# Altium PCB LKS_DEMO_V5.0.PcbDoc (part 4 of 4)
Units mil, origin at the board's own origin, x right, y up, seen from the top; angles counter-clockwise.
Board outline 5414.8 x 3354.56 mil, 2 copper layers (Top Layer, Bottom Layer); 131 components, 85 nets, 355 pads, 272 vias.
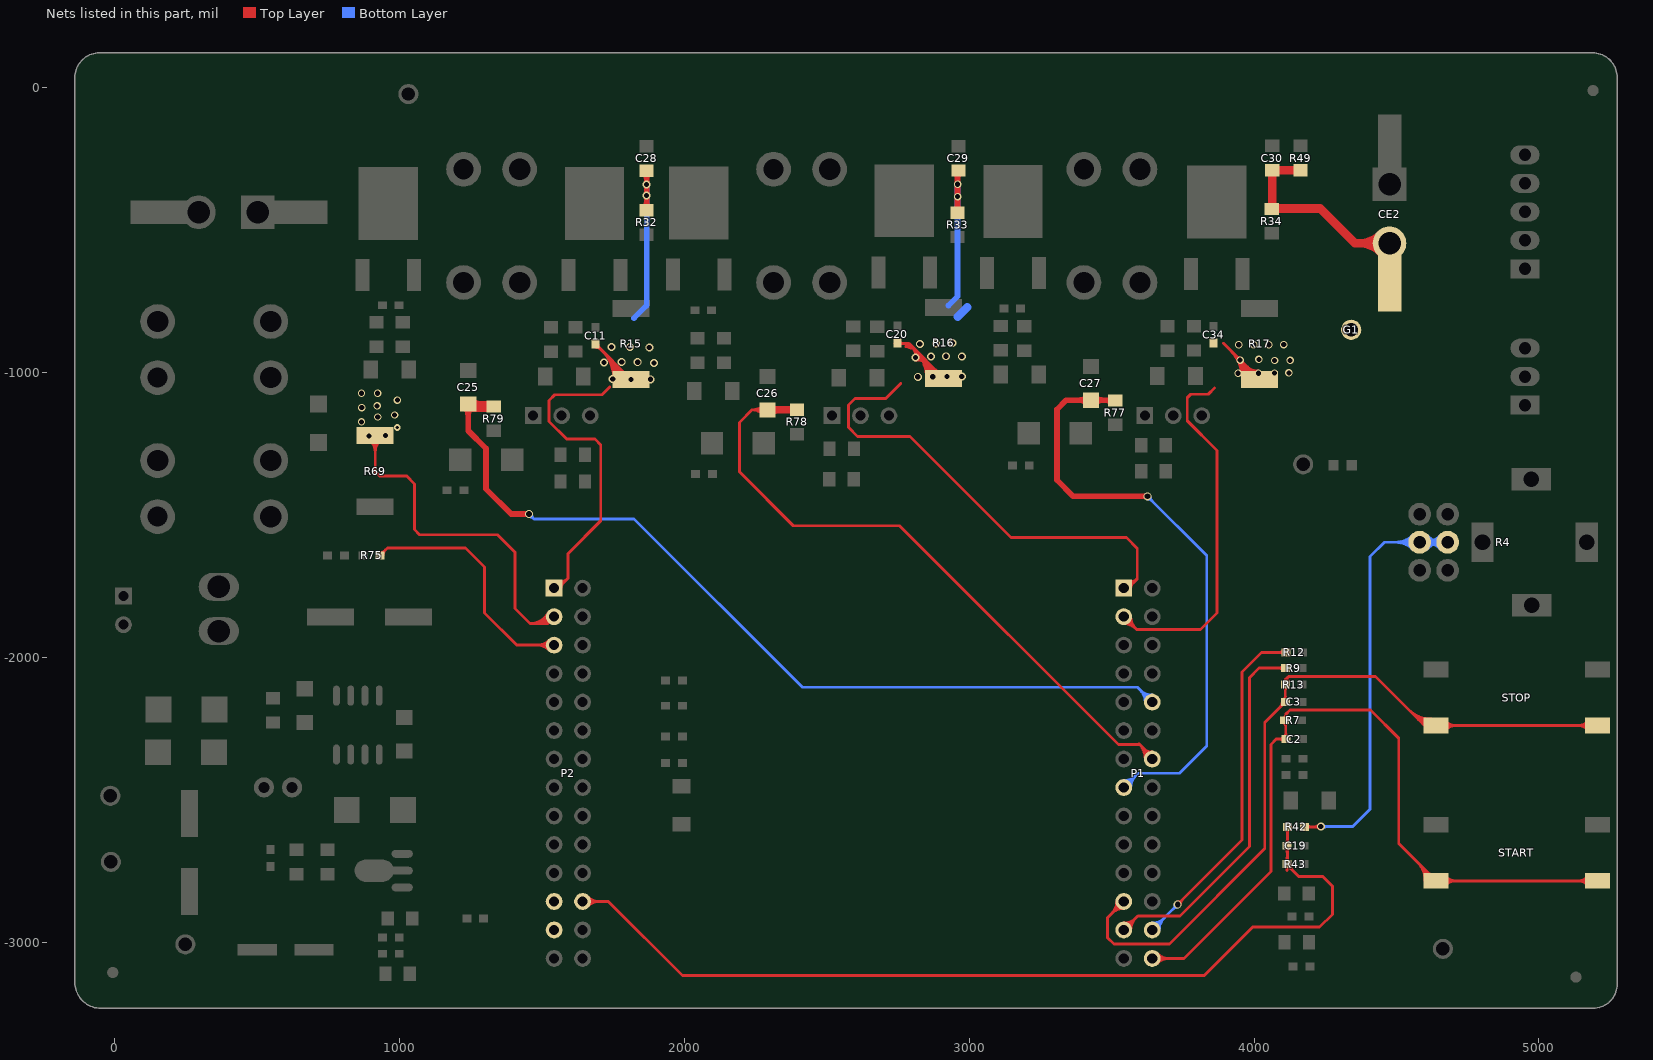
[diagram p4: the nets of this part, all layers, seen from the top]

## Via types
v1: diameter 26, hole 18, Top Layer to Bottom Layer, 117 vias
v2: diameter 28, hole 20, Top Layer to Bottom Layer, 77 vias
v3: diameter 28, hole 18, Top Layer to Bottom Layer, 73 vias
v4: diameter 23.62, hole 11.81, Top Layer to Bottom Layer, 5 vias

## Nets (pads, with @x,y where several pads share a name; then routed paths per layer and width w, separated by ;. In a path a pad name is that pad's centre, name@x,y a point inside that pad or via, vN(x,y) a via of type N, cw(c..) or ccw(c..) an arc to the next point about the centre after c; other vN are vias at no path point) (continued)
PGND: C11.2 C20.2 C28.1 C29.1 C30.1 C34.2 CE2.2 G1.1 P1.1 P1.2 P2.1 P2.2 R15.2 R16.1 R17.2 R32.1 R33.1 R34.1 R49.2 R69.1 | length 13563.9
  Top Layer w10: R69.1@914.27,-1220.9 914.27,-1347.89 930,-1363.63 1025.03,-1363.63 1052.09,-1390.69 1052.09,-1551.41 1070.11,-1569.43 1343.41,-1569.43 1404.57,-1630.58 1404.57,-1827.8 1457.84,-1881.07 1521.32,-1881.07 ; P2.1@1552.3,-1760.99 1590.81,-1722.48 ; C11.2@1686.48,-898.64 v3(1812.36,-1024.52) ; 1737.64,-1050.46 1710.19,-1077.91 1544.55,-1077.91 1524.89,-1097.56 1524.89,-1171.55 1586.49,-1233.15 1685.56,-1233.15 1706.23,-1253.82 1706.23,-1520.42 1590.81,-1635.84 1590.81,-1722.48 ; C20.2@2739.08,-898.48 2788.81,-898.48 R16.1@2909.76,-1019.43 ; 2759.24,-1038.12 2706.6,-1090.75 2598.05,-1090.75 2575.35,-1113.45 2575.35,-1191.92 2607.79,-1224.36 2791.94,-1224.36 3146.77,-1579.2 3551.29,-1579.2 3589.68,-1617.58 3589.68,-1723.64 ; P1.2@3542.25,-1856.82 3587.36,-1901.93 3812,-1901.93 3869.76,-1844.18 3869.76,-1273.79 3765.24,-1169.27 3765.24,-1088.38 3777.42,-1076.19 3838.74,-1076.19 3860.58,-1054.36 ; P1.1@3542.25,-1756.82 3556.5,-1756.82 3589.68,-1723.64 ; 3891.88,-896.92 R17.2@4018.89,-1023.93 ; 914.27,-1280.11 ccw(c855.06,-1280.11) 896.93,-1238.24 cw(c855.06,-1280.11) 914.27,-1280.11 ; 914.27,-1280.11 cw(c973.49,-1280.11) 931.61,-1238.24 ccw(c973.49,-1280.11) 914.27,-1280.11 ; 914.27,-1255.97 ccw(c879.2,-1255.97) 904,-1231.17 cw(c879.2,-1255.97) 914.27,-1255.97 ; 914.27,-1255.97 cw(c949.34,-1255.97) 924.54,-1231.17 ccw(c949.34,-1255.97) 914.27,-1255.97 ; 1590.81,-1722.49 cw(c1560.81,-1692.49) 1549.05,-1733.25 ccw(c1560.81,-1692.49) 1590.81,-1722.49 ; R15.2@1796.99,-1009.15 ccw(c1812.36,-993.79) 1812.36,-1015.52 cw(c1812.36,-993.79) R15.2@1796.99,-1009.15 ; R15.2@1796.99,-1009.15 cw(c1781.63,-1024.52) 1803.36,-1024.52 ccw(c1781.63,-1024.52) R15.2@1796.99,-1009.15 ; 2777.12,-901.14 ccw(c2799.64,-888.13) 2792.91,-913.25 ; 2777.12,-901.14 ccw(c2799.64,-888.13) 2792.91,-913.25 ; 2777.12,-901.14 ccw(c2799.64,-888.13) 2792.91,-913.25 ; 2778.18,-909.31 cw(c2778.18,-961.11) 2814.81,-924.48 ; 2778.18,-909.31 cw(c2778.18,-961.11) 2814.81,-924.48 ; 2778.18,-909.31 cw(c2778.18,-961.11) 2814.81,-924.48 ; 2778.18,-899.31 cw(c2778.18,-926.97) 2797.74,-907.41 ; 2778.18,-899.31 cw(c2778.18,-926.97) 2797.74,-907.41 ; 2778.18,-899.31 cw(c2778.18,-926.97) 2797.74,-907.41 ; 2778.25,-899.31 cw(c2776.95,-920.6) 2795.43,-909.93 ; 2778.25,-899.31 cw(c2776.95,-920.6) 2795.43,-909.93 ; 2778.25,-899.31 cw(c2776.95,-920.6) 2795.43,-909.93 ; 3567.05,-1881.62 ccw(c3542.25,-1906.42) 3542.25,-1871.34 cw(c3542.25,-1906.42) 3567.05,-1881.62 ; 3567.05,-1881.62 cw(c3591.85,-1856.82) 3556.78,-1856.82 ccw(c3591.85,-1856.82) 3567.05,-1881.62 ; 3584.12,-1898.69 ccw(c3542.25,-1940.56) 3542.25,-1881.34 cw(c3542.25,-1940.56) 3584.12,-1898.69 ; 3584.12,-1898.69 cw(c3625.99,-1856.82) 3566.78,-1856.82 ccw(c3625.99,-1856.82) 3584.12,-1898.69 ; 3589.67,-1723.64 cw(c3561.6,-1695.57) 3549.64,-1733.43 ccw(c3561.6,-1695.57) 3589.67,-1723.64 ; 1457.84,-1881.07 ccw(c1457.84,-1808.19) 1521,-1844.57 cw(c1457.84,-1808.19) 1457.84,-1881.07 ; 1475.14,-1881.07 ccw(c1475.14,-1818.16) 1529.66,-1849.56 cw(c1475.14,-1818.16) 1475.14,-1881.07 ; 1492.45,-1881.07 ccw(c1492.45,-1828.13) 1538.33,-1854.56 cw(c1492.45,-1828.13) 1492.45,-1881.07 ; 1509.75,-1881.07 ccw(c1509.75,-1838.09) 1546.99,-1859.55 cw(c1509.75,-1838.09) 1509.75,-1881.07 ; P2.1@1546.28,-1742.86 ccw(c1555.45,-1711.08) 1578.83,-1734.47 cw(c1555.45,-1711.08) P2.1@1546.28,-1742.86 ; P2.1@1566.78,-1756.82 cw(c1591.63,-1756.82) 1574.06,-1739.24 ccw(c1591.63,-1756.82) P2.1@1566.78,-1756.82 ; C11.2@1687.64,-911.18 cw(c1687.64,-938.66) 1707.07,-919.23 ccw(c1687.64,-938.66) C11.2@1687.64,-911.18 ; C11.2@1696.42,-902.4 ccw(c1711.33,-902.4) 1700.78,-912.94 cw(c1711.33,-902.4) C11.2@1696.42,-902.4 ; 1710,-922.16 cw(c1607.64,-1024.52) 1752.4,-1024.52 ccw(c1607.64,-1024.52) 1710,-922.16 ; 1727.07,-939.23 cw(c1641.78,-1024.52) 1762.4,-1024.52 ccw(c1641.78,-1024.52) 1727.07,-939.23 ; 1744.14,-956.3 cw(c1675.92,-1024.52) 1772.4,-1024.52 ccw(c1675.92,-1024.52) 1744.14,-956.3 ; 1761.21,-973.37 cw(c1710.07,-1024.52) 1782.4,-1024.52 ccw(c1710.07,-1024.52) 1761.21,-973.37 ; 1778.28,-990.44 cw(c1744.21,-1024.52) 1792.4,-1024.52 ccw(c1744.21,-1024.52) 1778.28,-990.44 ; C20.2@2753.73,-903.53 cw(c2765.92,-915.73) 2765.92,-898.48 ccw(c2765.92,-915.73) C20.2@2753.73,-903.53 ; C20.2@2753.73,-891.12 ccw(c2771.51,-873.34) 2771.51,-898.48 cw(c2771.51,-873.34) C20.2@2753.73,-891.12 ; 2794.48,-904.15 cw(c2751.96,-946.66) 2812.09,-946.66 ccw(c2751.96,-946.66) 2794.48,-904.15 ; 2806.96,-916.63 cw(c2702.58,-1021) 2850.19,-1021 ccw(c2702.58,-1021) 2806.96,-916.63 ; v3@2811.09,-955.66 cw(c2811.09,-1039.93) 2870.67,-980.34 ccw(c2811.09,-1039.93) v3@2811.09,-955.66 ; v3@2811.09,-945.66 cw(c2811.09,-1005.79) 2853.6,-963.27 ccw(c2811.09,-1005.79) v3@2811.09,-945.66 ; v3@2811.09,-935.66 cw(c2811.09,-971.65) 2836.53,-946.2 ccw(c2811.09,-971.65) v3@2811.09,-935.66 ; 2811.55,-921.22 cw(c2786.1,-946.66) 2822.09,-946.66 ccw(c2786.1,-946.66) 2811.55,-921.22 ; 2824.03,-933.7 cw(c2736.72,-1021) 2860.19,-1021 ccw(c2736.72,-1021) 2824.03,-933.7 ; 2841.1,-950.77 cw(c2770.87,-1021) 2870.19,-1021 ccw(c2770.87,-1021) 2841.1,-950.77 ; 2858.17,-967.84 cw(c2805.01,-1021) 2880.19,-1021 ccw(c2805.01,-1021) 2858.17,-967.84 ; 2875.24,-984.91 cw(c2839.15,-1021) 2890.19,-1021 ccw(c2839.15,-1021) 2875.24,-984.91 ; 2876.27,-985.94 ccw(c2921.84,-940.37) 2921.84,-1004.82 cw(c2921.84,-940.37) 2876.27,-985.94 ; R16.1@2893.34,-1003.01 ccw(c2921.84,-974.51) 2921.84,-1014.82 cw(c2921.84,-974.51) R16.1@2893.34,-1003.01 ; P1.1@3546.63,-1742.96 ccw(c3556.01,-1713.27) 3578.03,-1735.29 cw(c3556.01,-1713.27) P1.1@3546.63,-1742.96 ; P1.1@3566.78,-1756.82 cw(c3591.58,-1756.82) 3574.04,-1739.28 ccw(c3591.58,-1756.82) P1.1@3566.78,-1756.82 ; 3916.32,-921.36 cw(c3813.16,-1024.52) 3959.05,-1024.52 ccw(c3813.16,-1024.52) 3916.32,-921.36 ; 3933.39,-938.43 cw(c3847.31,-1024.52) 3969.05,-1024.52 ccw(c3847.31,-1024.52) 3933.39,-938.43 ; 3936.81,-941.84 cw(c3922.35,-956.3) 3942.8,-956.3 ccw(c3922.35,-956.3) 3936.81,-941.84 ; 3937.94,-942.97 ccw(c3950.8,-930.11) 3950.8,-948.3 cw(c3950.8,-930.11) 3937.94,-942.97 ; v1@3950.47,-955.5 cw(c3881.45,-1024.52) 3979.05,-1024.52 ccw(c3881.45,-1024.52) v1@3950.47,-955.5 ; v1@3950.8,-964.3 cw(c3950.8,-984.74) 3965.25,-970.29 ccw(c3950.8,-984.74) v1@3950.8,-964.3 ; v1@3958.8,-956.3 ccw(c3976.98,-956.3) 3964.12,-969.16 cw(c3976.98,-956.3) v1@3958.8,-956.3 ; 3967.54,-972.57 cw(c3915.59,-1024.52) 3989.05,-1024.52 ccw(c3915.59,-1024.52) 3967.54,-972.57 ; 3971.3,-976.34 ccw(c4015.34,-932.3) 4015.34,-994.58 cw(c4015.34,-932.3) 3971.3,-976.34 ; 3984.61,-989.64 cw(c3949.73,-1024.52) 3999.05,-1024.52 ccw(c3949.73,-1024.52) 3984.61,-989.64 ; 3988.37,-993.41 ccw(c4015.34,-966.44) 4015.34,-1004.58 cw(c4015.34,-966.44) 3988.37,-993.41
  Top Layer w20: R32.1@1866.99,-429.93 C28.1@1866.99,-290.99 ; R33.1@2958.76,-438.55 C29.1@2958.76,-300.89 ; 1866.99,-401.8 ccw(c1895.13,-401.8) 1875.23,-421.69 cw(c1895.13,-401.8) 1866.99,-401.8 ; 1866.99,-401.8 cw(c1838.86,-401.8) 1858.75,-421.69 ccw(c1838.86,-401.8) 1866.99,-401.8 ; 1866.99,-319.13 ccw(c1838.86,-319.13) 1858.75,-299.24 cw(c1838.86,-319.13) 1866.99,-319.13 ; 1866.99,-319.13 cw(c1895.13,-319.13) 1875.23,-299.24 ccw(c1895.13,-319.13) 1866.99,-319.13 ; C29.1@2950.41,-298.91 cw(c2930.24,-319.08) 2958.76,-319.08 ccw(c2930.24,-319.08) C29.1@2950.41,-298.91 ; R33.1@2950.54,-430.33 ccw(c2930.7,-410.49) 2958.76,-410.49 cw(c2930.7,-410.49) R33.1@2950.54,-430.33 ; 2958.76,-410.39 ccw(c2986.97,-410.39) 2967.02,-430.33 cw(c2986.97,-410.39) 2958.76,-410.39 ; 2958.76,-318.53 cw(c2986.5,-318.53) 2966.89,-298.91 ccw(c2986.5,-318.53) 2958.76,-318.53
  Top Layer w30: C30.1@4063.55,-289.6 4063.55,-423.88 4232.02,-423.88 4354.04,-545.9 CE2.2@4475.37,-545.9 ; C30.1@4063.76,-289.81 R49.2@4162.89,-289.81 ; 4369.02,-545.9 ccw(c4369.02,-439.54) 4444.22,-514.74 cw(c4369.02,-439.54) 4369.02,-545.9 ; 4369.02,-545.9 cw(c4369.02,-652.25) 4444.22,-577.05 ccw(c4369.02,-652.25) 4369.02,-545.9
  Bottom Layer w20: 1822.76,-808.82 1866.99,-764.58 v3@1866.99,-342.17 ; 2927,-764.3 2958.81,-732.5 v1(2958.81,-339)
  Bottom Layer w30: 2959.7,-803.54 2993.28,-769.96
  other v1: 892.64,-1222.76 949.94,-1220.9 866.13,-1173.28 922.99,-1156.02 982.37,-1149.02 866.77,-1122.82 921.06,-1117.07 991.96,-1096.63 866.12,-1072.37 922.84,-1072.41 3943.71,-1002.58 4015.34,-1002.58 4071.43,-1001.56 4121.77,-1001.22 4071.77,-957.63 4126.16,-956.96 3950.8,-956.3 4016.35,-953.59 3945.75,-902.24 3998.44,-901.89 4051.83,-902.23 4103.86,-901.89 2958.82,-382.12
  other v3: 1881.29,-1023.49 1747.93,-1022.53 2819.11,-1014.82 2871.72,-1014.82 2921.84,-1013.81 2973.45,-1013.31 1892.32,-966.4 1717.71,-964 1835.72,-963.53 1779.59,-962.57 2811.09,-946.66 2865.21,-943.66 2973.45,-943.15 2918.33,-942.65 1876.49,-912.2 1744.1,-910.76 1807.89,-910.28 2826.12,-899.06 2882.75,-898.05 2940.38,-896.55 1866.99,-378.39 1866.99,-339.36
  other v4: 991.83,-1192.69
RXD0: P1.13 R9.1 | length 1658
  Top Layer w10: P1.13@3542.25,-2956.82 3591.58,-2907.48 3739.73,-2907.48 3983.31,-2663.9 3983.31,-2071.55 4017.54,-2037.33 R9.1@4109.61,-2037.33 ; 3567.05,-2932.02 ccw(c3591.85,-2956.82) 3556.78,-2956.82 cw(c3591.85,-2956.82) 3567.05,-2932.02 ; 3567.05,-2932.02 cw(c3542.25,-2907.22) 3542.25,-2942.29 ccw(c3542.25,-2907.22) 3567.05,-2932.02 ; 3584.12,-2914.94 ccw(c3625.99,-2956.82) 3566.78,-2956.82 cw(c3625.99,-2956.82) 3584.12,-2914.94 ; 3584.12,-2914.94 cw(c3542.25,-2873.07) 3542.25,-2932.29 ccw(c3542.25,-2873.07) 3584.12,-2914.94 ; 4086.45,-2037.33 ccw(c4086.45,-2016.13) 4101.44,-2031.12 cw(c4086.45,-2016.13) 4086.45,-2037.33 ; 4086.45,-2037.33 cw(c4086.45,-2058.52) 4101.44,-2043.54 ccw(c4086.45,-2058.52) 4086.45,-2037.33
RXD1: P2.12
SPIN: C19.2 P2.26 R42.2 R43.2 | length 3870.8
  Top Layer w10: P2.26@1642.25,-2856.82 1732.3,-2856.82 1992.58,-3117.09 3825.04,-3117.09 3995.12,-2947.01 4229.81,-2947.01 4274.61,-2902.21 4274.61,-2803.4 4240.64,-2769.43 4156.27,-2769.43 R43.2@4115.46,-2728.62 ; R43.2@4109.02,-2731.94 cw(c4092.77,-2748.18) 4115.74,-2748.18 ; R43.2@4109.02,-2719.52 ccw(c4092.77,-2703.28) 4115.74,-2703.28 ; R42.2@4109.34,-2600.99 cw(c4092.05,-2618.27) 4116.49,-2618.27 ; C19.2@4109.54,-2655.11 ccw(c4092.74,-2638.32) 4116.49,-2638.32 ; R43.2@4110.98,-2719.52 ccw(c4097.68,-2706.22) 4116.49,-2706.22 ; R43.2@4111.22,-2722.41 ccw(c4098.48,-2709.68) 4116.49,-2709.68 ; 4115.74,-2745.67 cw(c4135.16,-2745.67) R43.2@4121.43,-2731.94 ; 4115.74,-2705.79 ccw(c4135.16,-2705.79) R43.2@4121.43,-2719.52 ; R43.2@4116.49,-2728.62 R42.2@4116.49,-2597.15 ; 4116.49,-2705.17 ccw(c4140.87,-2705.17) R43.2@4123.63,-2722.41 ; 4116.49,-2702.85 ccw(c4140.07,-2702.85) R43.2@4123.4,-2719.52 ; 4116.49,-2684.33 ccw(c4092.74,-2684.33) 4109.54,-2667.53 cw(c4094.55,-2682.52) 4115.74,-2682.52 cw(c4136.94,-2682.52) 4121.95,-2667.53 ccw(c4135.13,-2680.71) 4116.49,-2680.71 ; 4116.49,-2641.94 ccw(c4135.13,-2641.94) C19.2@4121.95,-2655.11 ; 4116.49,-2613.68 cw(c4134.44,-2613.68) R42.2@4121.75,-2600.99 ; R43.2@4117.43,-2737.4 cw(c4117.43,-2753.84) 4129.05,-2742.22 ; R43.2@4125.97,-2725.73 ccw(c4158.33,-2725.73) 4135.45,-2748.61 ; R43.2@4126.21,-2728.62 ccw(c4152.15,-2728.62) 4133.81,-2746.97 ; 1677.32,-2856.82 ccw(c1677.32,-2891.89) 1652.52,-2867.09 cw(c1677.32,-2891.89) 1677.32,-2856.82 ; 1677.32,-2856.82 cw(c1677.32,-2821.74) 1652.52,-2846.54 ccw(c1677.32,-2821.74) 1677.32,-2856.82 ; 1701.46,-2856.82 ccw(c1701.46,-2916.03) 1659.59,-2874.16 cw(c1701.46,-2916.03) 1701.46,-2856.82 ; 1701.46,-2856.82 cw(c1701.46,-2797.6) 1659.59,-2839.47 ccw(c1701.46,-2797.6) 1701.46,-2856.82
START1: C2.2 P1.28 R7.2 START.2 START.4 | length 4050.8
  Top Layer w10: P1.28@3642.25,-3056.82 3753.28,-3056.82 4058.77,-2751.32 4058.77,-2305.73 4077.8,-2286.71 C2.2@4110.99,-2286.71 4110.99,-2199.48 ; START.2@4619,-2785.42 START.4@5183.95,-2785.42 ; START.2@4638.66,-2784.03 4507.7,-2653.07 4507.7,-2283.96 4408.4,-2184.67 4125.8,-2184.67 4110.99,-2199.48 ; 3677.32,-3056.82 ccw(c3677.32,-3091.89) 3652.52,-3067.09 cw(c3677.32,-3091.89) 3677.32,-3056.82 ; 3677.32,-3056.82 cw(c3677.32,-3021.74) 3652.52,-3046.54 ccw(c3677.32,-3021.74) 3677.32,-3056.82 ; 3701.46,-3056.82 ccw(c3701.46,-3116.03) 3659.59,-3074.16 cw(c3701.46,-3116.03) 3701.46,-3056.82 ; 3701.46,-3056.82 cw(c3701.46,-2997.6) 3659.59,-3039.47 ccw(c3701.46,-2997.6) 3701.46,-3056.82 ; 4087.82,-2286.71 ccw(c4087.82,-2265.51) 4102.81,-2280.5 cw(c4087.82,-2265.51) 4087.82,-2286.71 ; 4087.82,-2286.71 cw(c4087.82,-2307.9) 4102.81,-2292.92 ccw(c4087.82,-2307.9) 4087.82,-2286.71 ; 4110.99,-2265.51 ccw(c4132.18,-2265.51) 4117.2,-2280.5 cw(c4132.18,-2265.51) 4110.99,-2265.51 ; 4110.99,-2265.51 cw(c4089.79,-2265.51) 4104.78,-2280.5 ccw(c4089.79,-2265.51) 4110.99,-2265.51 ; 4110.99,-2199.48 cw(c4092.87,-2199.48) 4103.89,-2213.86 ccw(c4092.87,-2199.48) 4110.99,-2199.48 ; R7.2@4103.02,-2227.04 cw(c4083.79,-2246.27) 4110.99,-2246.27 ccw(c4083.79,-2246.27) R7.2@4103.02,-2227.04 ; 4110.99,-2237.78 cw(c4126.18,-2237.78) 4115.44,-2227.04 ccw(c4126.18,-2237.78) 4110.99,-2237.78 ; 4110.99,-2203.88 ccw(c4126.18,-2203.88) 4115.44,-2214.62 cw(c4126.18,-2203.88) 4110.99,-2203.88 ; 4573.27,-2718.63 cw(c4507.87,-2784.03) 4600.35,-2784.03 ccw(c4507.87,-2784.03) 4573.27,-2718.63 ; 4590.34,-2735.7 cw(c4542.01,-2784.03) 4610.35,-2784.03 ccw(c4542.01,-2784.03) 4590.34,-2735.7 ; 4607.41,-2752.78 cw(c4576.16,-2784.03) 4620.35,-2784.03 ccw(c4576.16,-2784.03) 4607.41,-2752.78 ; START.2@4611.43,-2756.8 ccw(c4622.85,-2745.37) 4622.85,-2761.53 cw(c4622.85,-2745.37) START.2@4611.43,-2756.8 ; START.2@4663.31,-2775.19 ccw(c4688.01,-2750.48) 4688.01,-2785.42 cw(c4688.01,-2750.48) START.2@4663.31,-2775.19 ; START.2@4670.38,-2799.94 cw(c4705.42,-2834.98) 4705.42,-2785.42 ccw(c4705.42,-2834.98) START.2@4670.38,-2799.94 ; START.2@4670.38,-2768.12 ccw(c4712.16,-2726.34) 4712.16,-2785.42 cw(c4712.16,-2726.34) START.2@4670.38,-2768.12 ; 5132.09,-2785.42 ccw(c5132.09,-2726.34) 5173.87,-2768.12 cw(c5132.09,-2726.34) 5132.09,-2785.42 ; 5138.83,-2785.42 cw(c5138.83,-2834.98) 5173.87,-2799.94 ccw(c5138.83,-2834.98) 5138.83,-2785.42 ; 5156.23,-2785.42 ccw(c5156.23,-2750.48) 5180.94,-2775.19 cw(c5156.23,-2750.48) 5156.23,-2785.42
STOP1: C3.1 P1.12 R13.1 STOP.2 STOP.4 | length 4296.6
  Top Layer w10: P1.12@3542.25,-2856.82 3484.5,-2914.57 3484.5,-2983.05 3507.44,-3005.98 3702.22,-3005.98 4036.94,-2671.26 4036.94,-2228.44 C3.1@4109.35,-2156.04 R13.1@4109.35,-2095.34 4109.35,-2077.64 ; STOP.2@4617.02,-2258.15 4425.57,-2066.7 4120.28,-2066.7 ; STOP.2@4617.02,-2239 STOP.4@5183.95,-2239 ; 3500.38,-2898.69 ccw(c3458.51,-2856.82) 3517.72,-2856.82 cw(c3458.51,-2856.82) 3500.38,-2898.69 ; 3500.38,-2898.69 cw(c3542.25,-2940.56) 3542.25,-2881.34 ccw(c3542.25,-2940.56) 3500.38,-2898.69 ; 3517.45,-2881.62 ccw(c3492.65,-2856.82) 3527.72,-2856.82 cw(c3492.65,-2856.82) 3517.45,-2881.62 ; 3517.45,-2881.62 cw(c3542.25,-2906.42) 3542.25,-2871.34 ccw(c3542.25,-2906.42) 3517.45,-2881.62 ; 4109.35,-2134.85 ccw(c4130.54,-2134.85) 4115.55,-2149.83 cw(c4130.54,-2134.85) 4109.35,-2134.85 ; 4109.35,-2134.85 cw(c4088.15,-2134.85) 4103.14,-2149.83 ccw(c4088.15,-2134.85) 4109.35,-2134.85 ; 4109.35,-2116.54 ccw(c4088.15,-2116.54) 4103.14,-2101.55 cw(c4088.15,-2116.54) 4109.35,-2116.54 ; 4109.35,-2116.54 cw(c4130.54,-2116.54) 4115.55,-2101.55 ccw(c4130.54,-2116.54) 4109.35,-2116.54 ; 4109.35,-2077.64 ccw(c4122.81,-2077.64) 4114.66,-2088.35 cw(c4122.81,-2077.64) 4109.35,-2077.64 ; 4109.34,-2077.64 cw(c4095.88,-2077.64) 4104.03,-2088.35 ccw(c4095.88,-2077.64) 4109.34,-2077.64 ; 4109.35,-2077.64 4120.28,-2066.7 ; 4120.28,-2066.7 ccw(c4133.11,-2079.53) 4118.42,-2090.19 cw(c4133.11,-2079.53) 4120.28,-2066.7 ; 4091,-2174.39 ccw(c4072.65,-2156.04) 4098.6,-2156.04 cw(c4072.65,-2156.04) 4091,-2174.39 ; C3.1@4095.75,-2169.64 cw(c4107.38,-2181.27) 4107.38,-2164.82 ccw(c4107.38,-2181.27) C3.1@4095.75,-2169.64 ; R13.1@4110.33,-2096.06 cw(c4123.51,-2086.5) 4111.99,-2074.99 ccw(c4123.51,-2086.5) R13.1@4110.33,-2096.06 ; 4542.1,-2183.23 ccw(c4622.85,-2102.47) 4622.85,-2216.68 cw(c4622.85,-2102.47) 4542.1,-2183.23 ; 4559.17,-2200.3 ccw(c4622.85,-2136.61) 4622.85,-2226.68 cw(c4622.85,-2136.61) 4559.17,-2200.3 ; 4576.24,-2217.37 ccw(c4622.85,-2170.76) 4622.85,-2236.68 cw(c4622.85,-2170.76) 4576.24,-2217.37 ; 4593.31,-2234.44 ccw(c4622.85,-2204.9) 4622.85,-2246.68 cw(c4622.85,-2204.9) 4593.31,-2234.44 ; STOP.2@4663.31,-2248.02 cw(c4685.08,-2269.79) 4685.08,-2239 ccw(c4685.08,-2269.79) STOP.2@4663.31,-2248.02 ; STOP.2@4663.31,-2230.34 ccw(c4684.21,-2209.43) 4684.21,-2239 cw(c4684.21,-2209.43) STOP.2@4663.31,-2230.34 ; STOP.2@4670.38,-2255.09 cw(c4709.22,-2293.93) 4709.22,-2239 ccw(c4709.22,-2293.93) STOP.2@4670.38,-2255.09 ; STOP.2@4670.38,-2223.27 ccw(c4708.35,-2185.29) 4708.35,-2239 cw(c4708.35,-2185.29) STOP.2@4670.38,-2223.27 ; 5135.03,-2239 cw(c5135.03,-2293.93) 5173.87,-2255.09 ccw(c5135.03,-2293.93) 5135.03,-2239 ; 5135.89,-2239 ccw(c5135.89,-2185.29) 5173.87,-2223.27 cw(c5135.89,-2185.29) 5135.89,-2239 ; 5159.17,-2239 cw(c5159.17,-2269.79) 5180.94,-2248.02 ccw(c5159.17,-2269.79) 5159.17,-2239 ; 5160.04,-2239 ccw(c5160.04,-2209.43) 5180.94,-2230.34 cw(c5160.04,-2209.43) 5160.04,-2239
TXD0: P1.27 R12.2 | length 1717.5
  Top Layer w10: v2(3731.35,-2867.74) 3957.86,-2641.22 3957.86,-2050.75 4026.14,-1982.47 R12.2@4110.99,-1982.47 ; 3746.71,-2852.37 ccw(c3762.07,-2867.74) 3740.35,-2867.74 cw(c3762.07,-2867.74) 3746.71,-2852.37 ; 3746.71,-2852.37 cw(c3731.35,-2837.01) 3731.35,-2858.74 ccw(c3731.35,-2837.01) 3746.71,-2852.37 ; 4087.82,-1982.47 ccw(c4087.82,-1961.28) 4102.81,-1976.27 cw(c4087.82,-1961.28) 4087.82,-1982.47 ; 4087.82,-1982.47 cw(c4087.82,-2003.67) 4102.81,-1988.68 ccw(c4087.82,-2003.67) 4087.82,-1982.47
  Bottom Layer w10: P1.27@3642.25,-2956.82 v2(3731.35,-2867.74) ; 3667.05,-2932.02 ccw(c3691.85,-2956.82) 3656.78,-2956.82 cw(c3691.85,-2956.82) 3667.05,-2932.02 ; 3667.05,-2932.02 cw(c3642.25,-2907.22) 3642.25,-2942.29 ccw(c3642.25,-2907.22) 3667.05,-2932.02 ; 3684.12,-2914.94 ccw(c3725.99,-2956.82) 3666.78,-2956.82 cw(c3725.99,-2956.82) 3684.12,-2914.94 ; 3684.12,-2914.94 cw(c3642.25,-2873.07) 3642.25,-2932.29 ccw(c3642.25,-2873.07) 3684.12,-2914.94 ; 3715.95,-2883.11 cw(c3731.35,-2898.51) 3731.35,-2876.74 ccw(c3731.35,-2898.51) 3715.95,-2883.11 ; 3715.99,-2883.07 ccw(c3700.66,-2867.74) 3722.35,-2867.74 cw(c3700.66,-2867.74) 3715.99,-2883.07
TXD1: P2.13
VB1: C27.1 P1.8 R77.1 | length 2834.8
  Top Layer w20: R77.1@3511.39,-1097.1 C27.1@3427.06,-1097.1 3339.81,-1097.1 3307.7,-1129.21 3307.7,-1377.36 3364.86,-1434.52 v2(3625.43,-1434.52) ; 3385.07,-1097.1 ccw(c3385.07,-1057.08) 3413.37,-1085.38 cw(c3385.07,-1057.08) 3385.07,-1097.1 ; 3385.07,-1097.1 cw(c3385.07,-1137.11) 3413.37,-1108.82 ccw(c3385.07,-1137.11) 3385.07,-1097.1 ; 3469.04,-1097.1 ccw(c3469.04,-1137.11) 3440.74,-1108.82 cw(c3469.04,-1137.11) 3469.04,-1097.1 ; 3469.04,-1097.1 cw(c3469.04,-1057.08) 3440.74,-1085.38 ccw(c3469.04,-1057.08) 3469.04,-1097.1 ; 3478.84,-1097.1 cw(c3478.84,-1127.82) 3500.57,-1106.1 ccw(c3478.84,-1127.82) 3478.84,-1097.1 ; 3482.5,-1097.1 ccw(c3482.5,-1071.55) 3500.57,-1089.61 cw(c3482.5,-1071.55) 3482.5,-1097.1
  Bottom Layer w10: P1.8@3542.25,-2456.82 3592.55,-2406.52 3737.86,-2406.52 3833.52,-2310.86 3833.52,-1642.63 v2@3618.59,-1427.7 ; 3567.05,-2432.02 ccw(c3591.85,-2456.82) 3556.78,-2456.82 cw(c3591.85,-2456.82) 3567.05,-2432.02 ; 3567.05,-2432.02 cw(c3542.25,-2407.22) 3542.25,-2442.29 ccw(c3542.25,-2407.22) 3567.05,-2432.02 ; 3584.12,-2414.94 ccw(c3625.99,-2456.82) 3566.78,-2456.82 cw(c3625.99,-2456.82) 3584.12,-2414.94 ; 3584.12,-2414.94 cw(c3542.25,-2373.07) 3542.25,-2432.29 ccw(c3542.25,-2373.07) 3584.12,-2414.94 ; v2@3625.43,-1443.52 cw(c3625.43,-1465.2) 3640.77,-1449.87 ccw(c3625.43,-1465.2) v2@3625.43,-1443.52 ; v2@3634.43,-1434.52 ccw(c3656.21,-1434.52) 3640.81,-1449.92 cw(c3656.21,-1434.52) v2@3634.43,-1434.52
VB2: C26.1 P1.21 R78.1 | length 2902.4
  Top Layer w10: C26.1@2290.6,-1130.53 2237.61,-1130.53 ; P1.21@3639.99,-2347.67 3598.55,-2306.24 3523.56,-2306.24 2754.81,-1537.49 2382.07,-1537.49 2192.67,-1348.1 2192.67,-1175.46 2237.61,-1130.53 ; 2237.61,-1130.53 cw(c2237.61,-1180.19) 2273.97,-1146.36 ccw(c2237.61,-1180.19) 2237.61,-1130.53 ; 2240.41,-1130.53 ccw(c2240.41,-1082.31) 2274.51,-1116.41 cw(c2240.41,-1082.31) 2240.41,-1130.53 ; 2260.58,-1130.53 cw(c2260.58,-1158.82) 2281.29,-1139.55 ccw(c2260.58,-1158.82) 2260.58,-1130.53 ; 3595.51,-2303.2 cw(c3541.89,-2356.82) 3617.72,-2356.82 ccw(c3541.89,-2356.82) 3595.51,-2303.2 ; 3612.12,-2319.81 ccw(c3642.25,-2289.69) 3642.25,-2332.29 cw(c3642.25,-2289.69) 3612.12,-2319.81 ; 3612.58,-2320.27 cw(c3576.04,-2356.82) 3627.72,-2356.82 ccw(c3576.04,-2356.82) 3612.58,-2320.27
  Top Layer w25: C26.1@2290.6,-1130.53 R78.1@2395.27,-1130.53 ; 2369.82,-1130.53 ccw(c2369.82,-1108.43) 2385.45,-1124.06 cw(c2369.82,-1108.43) 2369.82,-1130.53 ; 2369.82,-1130.53 cw(c2369.82,-1152.63) 2385.45,-1137 ccw(c2369.82,-1152.63) 2369.82,-1130.53 ; C26.1@2303.65,-1141.61 cw(c2330.42,-1168.38) 2330.42,-1130.53 ccw(c2330.42,-1168.38) C26.1@2303.65,-1141.61 ; C26.1@2303.65,-1121.71 ccw(c2324.94,-1100.42) 2324.94,-1130.53 cw(c2324.94,-1100.42) C26.1@2303.65,-1121.71
VB3: C25.1 P1.19 R79.1 | length 3612.3
  Top Layer w20: C25.1@1240.79,-1110.76 1240.79,-1204.1 1303.28,-1266.58 1303.28,-1408.18 1391.82,-1496.73 v2(1454.04,-1496.74) ; 1240.79,-1150.77 ccw(c1200.78,-1150.77) 1229.07,-1122.48 cw(c1200.78,-1150.77) 1240.79,-1150.77 ; 1240.79,-1150.77 cw(c1280.81,-1150.77) 1252.51,-1122.48 ccw(c1280.81,-1150.77) 1240.79,-1150.77
  Top Layer w40: C25.1@1248.97,-1118.93 R79.1@1329.96,-1118.93 ; C25.1@1247.41,-1106.11 ccw(c1278.38,-1075.14) 1278.38,-1118.93 cw(c1278.38,-1075.14) C25.1@1247.41,-1106.11
  Bottom Layer w10: v2(1454.04,-1496.74) 1471.17,-1513.88 1823.28,-1513.88 2414.23,-2104.82 3590.26,-2104.82 P1.19@3642.25,-2156.82 ; 1469.4,-1512.1 ccw(c1454.04,-1527.47) 1454.04,-1505.74 cw(c1454.04,-1527.47) 1469.4,-1512.1 ; 1469.4,-1512.1 cw(c1484.76,-1496.74) 1463.04,-1496.74 ccw(c1484.76,-1496.74) 1469.4,-1512.1 ; 3600.38,-2114.94 ccw(c3642.25,-2073.07) 3642.25,-2132.29 cw(c3642.25,-2073.07) 3600.38,-2114.94 ; 3600.38,-2114.94 cw(c3558.51,-2156.82) 3617.72,-2156.82 ccw(c3558.51,-2156.82) 3600.38,-2114.94 ; 3617.45,-2132.02 ccw(c3642.25,-2107.22) 3642.25,-2142.29 cw(c3642.25,-2107.22) 3617.45,-2132.02 ; 3617.45,-2132.02 cw(c3592.65,-2156.82) 3627.72,-2156.82 ccw(c3592.65,-2156.82) 3617.45,-2132.02
VOL_ADC: P2.3 R75.2 | length 1221.5
  Top Layer w10: R75.2@930.89,-1641.8 957.3,-1615.38 1231.56,-1615.38 1298.35,-1682.17 1298.35,-1844.31 1410.85,-1956.82 P2.3@1542.25,-1956.82 ; 1483.03,-1956.82 ccw(c1483.03,-1897.6) 1524.91,-1939.47 cw(c1483.03,-1897.6) 1483.03,-1956.82 ; 1483.03,-1956.82 cw(c1483.03,-2016.03) 1524.91,-1974.16 ccw(c1483.03,-2016.03) 1483.03,-1956.82 ; 1507.18,-1956.82 ccw(c1507.18,-1921.74) 1531.98,-1946.54 cw(c1507.18,-1921.74) 1507.18,-1956.82 ; 1507.18,-1956.82 cw(c1507.18,-1991.89) 1531.98,-1967.09 ccw(c1507.18,-1991.89) 1507.18,-1956.82 ; R75.2@932.86,-1633.02 ccw(c932.86,-1616.57) 944.49,-1628.2 cw(c932.86,-1616.57) R75.2@932.86,-1633.02 ; R75.2@941.64,-1641.8 cw(c967.59,-1641.8) 949.24,-1623.45 ccw(c967.59,-1641.8) R75.2@941.64,-1641.8
ZB: R4.3 R4.5 R42.1 | length 2902.3
  Top Layer w10: R42.1@4176.57,-2594.78 v3@4233.23,-2594.78 ; R42.1@4184.74,-2600.99 cw(c4199.73,-2615.97) 4199.73,-2594.78 cw(c4199.73,-2573.58) R42.1@4184.74,-2588.57 ; 4210.44,-2594.78 ccw(c4210.44,-2570.48) v3@4227.62,-2587.66 ; 4214.07,-2594.78 cw(c4214.07,-2613.94) v3@4227.62,-2600.39
  Bottom Layer w10: v3(4233.99,-2594.03) 4346.2,-2594.03 4407.22,-2533.01 4407.22,-1645.54 4457.1,-1595.66 R4.5@4679.48,-1595.66 ; v3@4240.35,-2600.39 cw(c4255.71,-2615.75) 4255.71,-2594.03 cw(c4255.71,-2572.3) v3@4240.35,-2587.66 ; 4496.56,-1595.66 ccw(c4496.56,-1511.16) 4556.31,-1570.91 cw(c4496.56,-1511.16) 4496.56,-1595.66 ; 4496.56,-1595.66 cw(c4496.56,-1680.16) 4556.31,-1620.41 ccw(c4496.56,-1680.16) 4496.56,-1595.66 ; 4520.7,-1595.66 ccw(c4520.7,-1535.3) 4563.38,-1577.98 cw(c4520.7,-1535.3) 4520.7,-1595.66 ; 4520.7,-1595.66 cw(c4520.7,-1656.02) 4563.38,-1613.34 ccw(c4520.7,-1656.02) 4520.7,-1595.66 ; R4.3@4594.98,-1595.66 ccw(c4594.98,-1511.16) 4654.73,-1570.91 cw(c4594.98,-1511.16) R4.3@4594.98,-1595.66 ; R4.3@4594.98,-1595.66 cw(c4594.98,-1680.16) 4654.73,-1620.41 ccw(c4594.98,-1680.16) R4.3@4594.98,-1595.66 ; R4.3@4619.12,-1595.66 ccw(c4619.12,-1535.3) 4661.8,-1577.98 cw(c4619.12,-1535.3) R4.3@4619.12,-1595.66 ; R4.3@4619.12,-1595.66 cw(c4619.12,-1656.02) 4661.8,-1613.34 ccw(c4619.12,-1656.02) R4.3@4619.12,-1595.66 ; R4.5@4641.41,-1595.66 ccw(c4641.41,-1656.02) 4598.73,-1613.34 cw(c4641.41,-1656.02) R4.5@4641.41,-1595.66 ; R4.5@4641.41,-1595.66 cw(c4641.41,-1535.3) 4598.73,-1577.98 ccw(c4641.41,-1535.3) R4.5@4641.41,-1595.66 ; R4.5@4665.55,-1595.66 ccw(c4665.55,-1680.16) 4605.8,-1620.41 cw(c4665.55,-1680.16) R4.5@4665.55,-1595.66 ; R4.5@4665.55,-1595.66 cw(c4665.55,-1511.16) 4605.8,-1570.91 ccw(c4665.55,-1511.16) R4.5@4665.55,-1595.66
pads on no net: R4.0

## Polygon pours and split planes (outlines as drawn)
PGND on Top Layer "Bottom Layer-No Net" (solid, remove dead copper, pour order 85): 4233.08,-503.67 4579.06,-503.67 4607.57,-532.18 4618.36,-542.97 4618.36,-835.01 4618.36,-837.32 4448.84,-1006.84 4266.98,-1006.84 4230,-1006.84
GND on Top Layer "Bottom Layer-No Net" (solid, remove dead copper, pour order 82): 616.46,-1697.87 610.61,-1704.31 610.61,-1788.02 610.61,-1918.11 619.37,-1927.78 646.78,-1958.05 800.76,-1958.05 866.67,-1958.05 877.17,-1946.46 889.99,-1932.3 889.99,-1696.59
NetCF1_1 on Top Layer "Bottom Layer-No Net" (solid, remove dead copper, pour order 78): 894.61,-1772.34 902.96,-1763.61 1123.41,-1763.61 1123.41,-2120.67 1096.41,-2148.86 1093.84,-2151.54 969.14,-2151.54 969.14,-2053.57 969.79,-2052.89 967.22,-2050.2 896.53,-2050.2 896.53,-1765.24 894.39,-1763.01
+48V on Top Layer "Bottom Layer-No Net" (solid, remove dead copper, pour order 91): 512.88,84.23 505.13,84.23 474.13,53.23 472.58,51.68 472.58,-283.09 472.58,-424.13 395.09,-501.62 155.6,-741.11 155.6,-820.65 155.6,-1074.27 173.45,-1092.13 178.1,-1096.78 512.88,-1096.78 711.26,-1096.78 731.41,-1076.63 756.21,-1051.83 756.21,-1013.08 756.21,-558.97 801.15,-514.02 804.26,-517.13 901.89,-517.13 1021.23,-517.13 1056.89,-481.47 1064.63,-473.72 1064.63,-272.24 1064.63,-196.3 1112.68,-148.25 1371.51,-148.25 1817.87,-148.25 1856.62,-187 1962.01,-292.39 1962.01,-362.13 2130.95,-362.13 2134.05,-359.04 2148,-345.09 2148,-253.64 2148,-227.3 2177.45,-197.85 2227.04,-148.25 2377.38,-148.25 2932.24,-148.25 2975.63,-191.65 3054.68,-270.69 3054.68,-340.44 3062.43,-340.44 3085.68,-363.68 3088.77,-366.78 3223.61,-366.78 3240.66,-366.78 3248.41,-359.03 3248.41,-279.99 3248.41,-200.95 3288.71,-160.65 3293.36,-156 3939.66,-156 4000.1,-156 4045.05,-200.95 4046.6,-199.4 4220.19,-199.4 4248.09,-199.4 4272.88,-224.2 4324.03,-275.34 4324.03,-303.24 4324.03,-338.89 4339.53,-354.39 4344.17,-359.03 4643.31,-359.03 4665.01,-359.03 4691.35,-332.69 4691.34,-332.68 4691.34,36.18 4691.34,68.74 4610.76,149.32
GND on Top Layer "Bottom Layer-No Net" (solid, remove dead copper, pour order 95): 135.26,-1248.11 85.24,-1198.09 85.24,-1056.74 85.24,-591.37 158.08,-518.53 310.31,-366.3 310.31,-272.79 310.31,-230.39 275.52,-195.59 261.38,-181.46 80.89,-181.46 -13.71,-181.46 -88.73,-256.48 -121.35,-289.1 -121.35,-1249.2
GND on Top Layer "Bottom Layer-No Net" (solid, remove dead copper, pour order 105): 787.74,-2679.11 777.5,-2689.35 777.5,-2826.88 1228.84,-2826.88 1274.92,-2780.79 1286.62,-2769.09 1286.62,-2647.66 803.1,-2647.66 783.35,-2667.41
GND on Top Layer "Bottom Layer-No Net" (solid, remove dead copper, pour order 104): 916.55,-1427.29 920.84,-1427.29 974.03,-1482.9 982.61,-1491.87 982.61,-1566.3 982.61,-1572.58 968.02,-1587.82 967.17,-1586.93 600.02,-1586.93 -89.68,-1586.93 -182.32,-1490.07 -117.97,-1422.8 -117.97,-1296.35 -117.97,-1241.64 -108.54,-1231.78 -100.83,-1223.71 650.63,-1223.71 683.24,-1223.71 700.39,-1241.64 725.26,-1267.64 725.26,-1404.87 725.26,-1425.5 724.4,-1426.4
AX on Top Layer "Bottom Layer-No Net" (solid, remove dead copper, pour order 103): 1160.61,-219.63 1129.04,-251.2 1129.04,-277.03 1129.04,-559.01 1093.88,-594.17 1061.59,-626.45 1061.59,-658.02 1061.59,-701.79 1067.33,-707.53 1107.51,-747.71 1388.77,-747.71 1479.18,-747.71 1497.83,-729.05 1503.57,-723.31 1503.57,-640.8 1503.57,-598.47 1517.19,-584.85 1527.24,-574.8 1604.01,-574.8 1652.8,-574.8 1682.23,-545.38 1687.97,-539.64 1687.97,-337.3 1687.97,-277.75 1680.07,-269.86 1662.85,-252.64 1489.22,-252.64 1456.93,-252.64 1423.21,-218.92
BX on Top Layer "Bottom Layer-No Net" (solid, remove dead copper, pour order 102): 2248.2,-218.21 2216.63,-249.78 2216.63,-275.61 2216.63,-557.59 2181.47,-592.74 2149.18,-625.03 2149.18,-656.6 2149.18,-700.37 2154.92,-706.11 2195.1,-746.29 2476.36,-746.29 2566.77,-746.29 2585.42,-727.63 2591.16,-721.89 2591.16,-639.38 2591.16,-597.05 2604.78,-583.43 2614.83,-573.38 2691.6,-573.38 2740.39,-573.38 2769.82,-543.95 2775.56,-538.22 2775.56,-335.88 2775.56,-276.33 2767.66,-268.44 2750.44,-251.22 2576.81,-251.22 2544.52,-251.22 2510.8,-217.49
CX on Top Layer "Bottom Layer-No Net" (solid, remove dead copper, pour order 101): 3351.02,-205.56 3319.44,-237.13 3319.44,-262.96 3319.44,-544.94 3284.29,-580.09 3252,-612.38 3252,-643.95 3252,-687.72 3257.74,-693.46 3297.92,-733.64 3579.18,-733.64 3669.58,-733.64 3688.24,-714.98 3693.98,-709.24 3693.98,-626.73 3693.98,-584.4 3707.6,-570.77 3717.65,-560.73 3794.42,-560.73 3843.21,-560.73 3872.63,-531.3 3878.37,-525.56 3878.37,-323.23 3878.37,-263.68 3870.48,-255.78 3853.26,-238.56 3679.63,-238.56 3647.34,-238.56 3613.62,-204.84
PGND on Top Layer "Bottom Layer-No Net" (solid, remove dead copper, pour order 97): 831.64,-1041.72 831.64,-1207.2 837.51,-1215.14 869.82,-1258.82 985.82,-1258.82 1001.49,-1258.82 1005.4,-1253.53 1032.32,-1217.12 1032.32,-1096 1032.32,-1079.45 1003.93,-1041.06
GND on Top Layer "Bottom Layer-No Net" (solid, remove dead copper, pour order 92): 127.5,-2733.94 401.08,-2733.94 407.48,-2742.54 417.55,-2756.04 417.55,-2775.69 417.55,-2824.8 422.12,-2830.94 451.4,-2870.23 528.26,-2870.23 540.16,-2870.23 554.8,-2889.86 559.37,-2895.99 559.37,-2977.04 559.37,-3155.07 554.79,-3161.21 365.39,-3161.21 294.94,-3161.21 126.59,-2935.3
+15V on Top Layer "Bottom Layer-No Net" (solid, remove dead copper, pour order 89): 194.27,-2352.76 195.21,-2353.81 195.21,-2401.34 195.21,-2417.18 204.69,-2427.74 212.27,-2436.19 291.88,-2436.19 436.87,-2436.19 460.57,-2409.78 467.19,-2402.4 538.27,-2402.4 549.64,-2402.4 558.17,-2411.9 560.07,-2414.01 560.07,-2538.61 560.07,-2646.31 543.96,-2664.26 518.37,-2692.77 196.16,-2692.77 111.82,-2692.77 85.28,-2663.2 54.96,-2629.41 54.96,-2350.66
GND on Top Layer "Bottom Layer-No Net" (solid, remove dead copper, pour order 106): 900.27,-2405.33 900.7,-2405.9 900.7,-2594.65 1081.72,-2594.65 1082.15,-2595.22 1080.87,-2593.52 1080.87,-2405.33
DM_IN on Top Layer "Top Layer-No Net" (solid, pour order 107): 130.78,-1834.97 521.99,-1834.97 521.09,-1835.57 521.09,-1999.76 131.69,-1999.76 130.78,-2000.36
PGND on Top Layer "Top Layer-No Net" (solid, remove dead copper, pour order 86): 1674.38,-885.58 1673.96,-886.02 1673.96,-938.86 1673.96,-948.91 1712.99,-989.96 1714.65,-991.7 1714.65,-1049.35 1714.65,-1055.65 1731.81,-1073.69 1879.29,-1073.69 1902.44,-1073.69 1917.28,-1058.08 1919.77,-1055.46 1919.77,-931.87 1919.77,-886.89 1918.52,-885.58
AI on Top Layer "Top Layer-No Net" (solid, remove dead copper, pour order 84): 1687.06,-602.61 1681.82,-607.85 1681.82,-762.43 1681.82,-781.65 1687.93,-787.76 1699.73,-799.55 1857.38,-799.55 1889.88,-799.55 1889.92,-799.52 1900.61,-788.82 1900.61,-715.71 1900.61,-608.72 1892.75,-600.85
BI on Top Layer "Top Layer-No Net" (solid, remove dead copper, pour order 83): 2780.41,-593.77 2783.65,-590.53 2960.49,-590.53 2985.88,-590.53 2990.56,-595.22 3000.33,-604.98 3000.33,-762.4 3000.33,-798.34 2995.25,-803.41 2994.86,-803.8 2767.13,-803.8 2767.13,-595.72 2769.09,-593.77
PGND on Top Layer "Top Layer-No Net" (solid, remove dead copper, pour order 81): 2747.44,-880.01 2734.41,-893.04 2734.41,-970.22 2734.41,-1044.38 2741.93,-1051.9 2759.46,-1069.43 2951.91,-1069.43 2990.01,-1069.43 3006.53,-1052.9 3006.53,-930.13 3006.53,-894.54 2991.5,-879.51
CI on Top Layer "Top Layer-No Net" (solid, remove dead copper, pour order 79): 3876.52,-598.22 3881.8,-592.94 4102.94,-592.94 4126.1,-592.94 4133.82,-600.66 4141.54,-608.38 4141.54,-727.6 4141.54,-800.5 4134.68,-807.36 4131.25,-803.93 3875.66,-803.93
PGND on Top Layer "Top Layer-No Net" (solid, remove dead copper, pour order 75): 3857.99,-881.27 4134.22,-881.27 4140.18,-887.7 4144.58,-892.43 4144.58,-935.36 4144.58,-1076.68 4143.64,-1077.69 4140.81,-1080.73 3910.41,-1080.73 3854.85,-1080.73 3851.08,-1076.68 3843.86,-1068.9 3843.86,-880.93
GND on Top Layer "Bottom Layer-No Net" (solid, remove dead copper, pour order 77): 405.44,-2733.95 551.08,-2733.95 558.52,-2741.39 559.63,-2742.5 559.63,-2904.86 449.66,-2904.86 383.16,-2838.35 380.93,-2836.13 380.93,-2733.58
+5V on Top Layer "Bottom Layer-No Net" (solid, remove dead copper, pour order 80): 973.77,-2845.79 973.77,-2849.6 948.67,-2874.7 946.49,-2876.88 946.49,-3007.81 946.49,-3045.99 936.67,-3055.81 935.58,-3056.9 854.3,-3056.9 852.66,-3056.9 834.66,-3074.9 818.3,-3091.27 818.3,-3155.64 818.3,-3182.35 810.1,-3190.55 806.82,-3193.83 693.37,-3193.83 658.48,-3193.83 651.92,-3187.27 643.18,-3178.54 643.18,-3020.9 643.18,-2907.96 613.19,-2877.96 607.71,-2872.49 607.71,-2753.58 761.55,-2753.58 762.1,-2754.13 769.74,-2761.77 769.74,-2826.69 774.65,-2826.69 797.02,-2849.06
+15V on Bottom Layer "Bottom Layer-No Net" (solid, remove dead copper, pour order 76): 1155.6,-1736.55 1272.58,-1736.55 1288.91,-1720.22 1300.66,-1708.47 1300.66,-1557.37 1300.66,-1507.49 1296.93,-1503.75 1292.05,-1498.88 1197.17,-1498.88 1162.2,-1498.88 1140.67,-1520.4 1136.66,-1524.41 1136.66,-1736.55
+48V on Bottom Layer "Bottom Layer-No Net" (solid, remove dead copper, pour order 90): 510.3,82.49 502.55,82.49 471.55,51.49 470,49.94 470,-284.83 470,-425.87 392.51,-503.37 153.02,-742.86 153.02,-822.39 153.02,-1076.02 170.87,-1093.87 175.52,-1098.52 510.3,-1098.52 708.68,-1098.52 728.83,-1078.37 753.63,-1053.58 753.63,-1014.83 753.63,-560.71 798.57,-515.77 801.68,-518.88 899.31,-518.88 1018.65,-518.88 1054.31,-483.21 1062.05,-475.47 1062.05,-273.99 1062.05,-198.04 1110.1,-150 1368.93,-150 1815.29,-150 1854.04,-188.74 1959.43,-294.13 1959.43,-363.88 2128.37,-363.88 2131.47,-360.78 2145.42,-346.83 2145.42,-255.39 2145.42,-229.04 2174.87,-199.59 2224.46,-150 2374.8,-150 2929.66,-150 2973.05,-193.39 3052.1,-272.44 3052.1,-342.18 3059.85,-342.18 3083.1,-365.43 3086.19,-368.53 3221.03,-368.53 3238.08,-368.53 3245.83,-360.78 3245.83,-281.74 3245.83,-202.69 3286.13,-162.39 3290.78,-157.74 3937.08,-157.74 3997.52,-157.74 4042.47,-202.69 4044.02,-201.14 4217.61,-201.14 4245.51,-201.14 4270.3,-225.94 4321.45,-277.09 4321.45,-304.98 4321.45,-340.63 4336.95,-356.13 4341.59,-360.77 4640.73,-360.77 4662.43,-360.77 4688.77,-334.43 4688.76,-334.42 4688.76,34.43 4688.76,67 4608.18,147.58
PGND on Bottom Layer "Top Layer-No Net" (solid, remove dead copper, pour order 109): 867.51,-1255.03 829.57,-1217.09 829.57,-1128.11 829.57,-808.36 850.08,-787.84 855.95,-781.98 1003.98,-781.98 1022.51,-781.98 1059.62,-819.09 1067.49,-826.96 1449.66,-826.96 1493.28,-826.96 1587.55,-732.69 1591.84,-728.4 2090.78,-728.4 2090.99,-728.4 2182.14,-819.55 2182.23,-819.64 2446.3,-819.64 2599.07,-819.64 2676.55,-742.16 2695.37,-723.34 3143.56,-723.34 3173.98,-723.34 3243.49,-792.84 3256.51,-805.87 3701.09,-805.87 3706.16,-805.87 3780.74,-731.3 3784.36,-727.68 4096.43,-727.68 4108.74,-727.68 4173.18,-663.24 4218.07,-618.35 4218.07,-540.15 4218.07,-514.08 4228.21,-503.94 4234,-498.15 4366.5,-498.15 4613.98,-498.15 4632.08,-516.25 4635.13,-519.3 4635.13,-918.11 4635.13,-1023.82 4620.65,-1038.3 4606.02,-1052.93 4067.23,-1052.93 1134.67,-1052.93 1093.52,-1094.08 1019.17,-1168.42 1019.17,-1239.48 1019.17,-1241.24 1005.38,-1255.03
GND on Bottom Layer "Top Layer-No Net" (solid, remove dead copper, pour order 87): 501.73,-1684.3 901.61,-2128.78 990.93,-2128.78 990.93,-1686.83 977.48,-1671.89
GND on Bottom Layer "Bottom Layer-No Net" (solid, remove dead copper, pour order 96): -117.12,-1188.76 -117.12,-1444.81 -89.07,-1471.14 214.38,-1755.91 1076.3,-1755.91 1080.12,-1755.91 1094.15,-1742.75 1092.87,-1741.55 1092.87,-1621.9 1092.87,-1448.4 1115.82,-1426.87 1027.84,-1344.31 809.82,-1344.31 781.77,-1344.31 696.34,-1264.14 646.61,-1217.47 609.64,-1217.47
GND on Bottom Layer "Bottom Layer-No Net" (solid, remove dead copper, pour order 94): 136.87,-1247.3 86.85,-1197.28 86.85,-1055.93 86.85,-590.56 159.69,-517.72 311.92,-365.49 311.92,-271.98 311.92,-229.58 277.13,-194.78 263,-180.65 82.5,-180.65 -12.09,-180.65 -87.12,-255.67 -119.74,-288.29 -119.74,-1248.39
AX on Bottom Layer "Bottom Layer-No Net" (solid, remove dead copper, pour order 100): 1160.61,-219.63 1129.04,-251.2 1129.04,-277.03 1129.04,-559.01 1093.88,-594.17 1061.59,-626.45 1061.59,-658.02 1061.59,-701.79 1067.33,-707.53 1107.51,-747.71 1388.77,-747.71 1479.18,-747.71 1497.83,-729.05 1503.57,-723.31 1503.57,-640.8 1503.57,-598.47 1517.19,-584.85 1527.24,-574.8 1604.01,-574.8 1652.8,-574.8 1682.23,-545.38 1687.97,-539.64 1687.97,-337.3 1687.97,-277.75 1680.07,-269.86 1662.85,-252.64 1489.22,-252.64 1456.93,-252.64 1423.21,-218.92
BX on Bottom Layer "Bottom Layer-No Net" (solid, remove dead copper, pour order 99): 2249.18,-218.02 2217.61,-249.59 2217.61,-275.42 2217.61,-557.39 2182.46,-592.55 2150.17,-624.84 2150.17,-656.41 2150.17,-700.18 2155.91,-705.91 2196.09,-746.09 2477.35,-746.09 2567.75,-746.09 2586.41,-727.44 2592.15,-721.7 2592.15,-639.19 2592.15,-596.85 2605.77,-583.23 2615.81,-573.19 2692.59,-573.19 2741.38,-573.19 2770.8,-543.76 2776.54,-538.02 2776.54,-335.69 2776.54,-276.14 2768.65,-268.24 2751.43,-251.02 2577.8,-251.02 2545.51,-251.02 2511.79,-217.3
CX on Bottom Layer "Bottom Layer-No Net" (solid, remove dead copper, pour order 98): 3349.09,-204.92 3317.52,-236.49 3317.52,-262.32 3317.52,-544.3 3282.37,-579.45 3250.08,-611.74 3250.08,-643.31 3250.08,-687.08 3255.82,-692.82 3296,-732.99 3577.26,-732.99 3667.66,-732.99 3686.32,-714.34 3692.06,-708.6 3692.06,-626.09 3692.06,-583.76 3705.68,-570.13 3715.72,-560.09 3792.5,-560.09 3841.29,-560.09 3870.71,-530.66 3876.45,-524.92 3876.45,-322.59 3876.45,-263.04 3868.56,-255.14 3851.34,-237.92 3677.71,-237.92 3645.42,-237.92 3611.7,-204.2
DM_IN on Bottom Layer "Top Layer-No Net" (solid, pour order 108): 132.2,-1839.85 132.58,-1840.1 519.08,-1840.1 519.08,-2000.89 518.7,-2001.15 132.2,-2001.15
GND on Bottom Layer "Top Layer-No Net" (solid, remove dead copper, pour order 88): 976.12,-1404.24 976.12,-1337.19 1032.41,-1245.37 1073.51,-1178.33 1186.1,-1178.33 3131.29,-1178.33 3175.96,-1251.2 3175.96,-1491.46 1121.01,-1491.46 1056.54,-1596.62
GND on Bottom Layer "Bottom Layer-No Net" (solid, remove dead copper, pour order 93): 173.48,-2598.58 151.78,-2620.28 151.78,-2889.96 151.78,-2893.06 281.97,-3023.25 514.46,-3255.75 2237.93,-3255.75 4596.88,-3255.75 5173.45,-2679.18 5195.14,-2657.48 5195.14,-1411.36 5195.14,-1329.69 5176.55,-1311.1 5168.53,-1303.08 4059.9,-1303.08 3907.49,-1303.08 3878.61,-1331.96 3872.2,-1338.37 3872.2,-1498.8 3872.2,-1540.52 3841.71,-1571.01 3755.07,-1657.65 2282.25,-1657.65 1919.66,-1657.65 1865.11,-1712.2 1781.69,-1795.61 1781.69,-2041.08 1781.69,-2532.54 1716.63,-2597.61
PGND on Bottom Solder "Top Layer-No Net" (solid): 878.3,-825.25 856.06,-847.49 856.06,-940.07 856.06,-1183.38 881.14,-1208.46 894.01,-1221.34 980.76,-1221.34 1012.62,-1221.34 1034.3,-1199.65 1059.49,-1174.47 1059.49,-1128.11 1059.49,-1068.74 1095.98,-1032.25 1100.16,-1028.07 2152.26,-1028.07 4553.06,-1028.07 4592.23,-988.89 4595.2,-985.92 4595.2,-686.16 4595.2,-545.58 4587.02,-537.4 4581.07,-531.45 4341.56,-531.45 4294.7,-531.45 4273.88,-552.27 4254.54,-571.61 4254.54,-610.29 4254.54,-633.35 4210.65,-677.23 4146.68,-741.2 4069.33,-741.2 4068.44,-741.2 3984.03,-825.61
+48V on Bottom Solder "Bottom Layer-No Net" (solid): 4231.46,-112.26 4271.65,-112.26 4345.78,-195.43 4401.21,-257.61 4641.64,-257.61 4663.81,-257.61 4687.37,-231.17 4694.99,-222.63 4694.99,-29.88 4694.99,38.52 4672.12,64.17 4657.06,81.07 4511.96,81.07
+48V on Bottom Solder "Top Layer-No Net" (solid): 548.11,47.29 548.11,-326.28 548.11,-364.03 305.69,-606.46 263.96,-648.19 263.96,-858.82 263.96,-1059.51 275.88,-1071.44 585.87,-1071.44 659.39,-1071.44 683.24,-1047.59 697.15,-1033.68 697.15,-771.39 697.15,-588.57 772.65,-513.07 800.47,-485.25 937.58,-485.25 967.39,-485.25 1011.1,-441.53 1030.97,-421.66 1030.97,-246.8 1030.97,-203.08 1080.65,-153.4 1104.5,-129.56 1923.17,-129.56 4528.23,-129.56 4544.13,-113.66 4567.98,-89.82 4567.98,35.37 4567.98,59.21 4548.11,79.08 4546.12,81.07 3182.98,81.07 561.89,81.07 548.02,67.21
AX on Bottom Solder "Top Layer-No Net" (solid): 1175.71,-240.45 1163.23,-252.92 1163.23,-280.37 1163.23,-566.11 1115.81,-613.52 1109.57,-619.76 1109.57,-694.63 1109.57,-712.1 1129.54,-732.06 1130.79,-733.31 1425.26,-733.31 1458.95,-733.31 1473.92,-718.34 1482.65,-709.6 1482.65,-609.78 1482.65,-581.08 1505.11,-558.62 1541.3,-522.44 1749.67,-522.44 1767.14,-522.44 1779.62,-509.96 1779.62,-386.43 1779.62,-320.3 1763.4,-304.08 1750.92,-291.6 1634.88,-291.6 1467.68,-291.6 1415.27,-239.2
BX on Bottom Solder "Top Layer-No Net" (solid): 2253.44,-232.18 2240.96,-244.66 2240.96,-272.11 2240.96,-557.84 2193.55,-605.26 2187.31,-611.5 2187.31,-686.36 2187.31,-703.83 2207.27,-723.8 2208.52,-725.04 2502.99,-725.04 2536.68,-725.04 2551.65,-710.07 2560.39,-701.34 2560.39,-601.52 2560.39,-572.82 2582.85,-550.36 2619.03,-514.17 2827.41,-514.17 2844.87,-514.17 2857.35,-501.69 2857.35,-378.17 2857.35,-312.04 2841.13,-295.82 2828.65,-283.34 2712.61,-283.34 2545.41,-283.34 2493.01,-230.93
CX on Bottom Solder "Top Layer-No Net" (solid): 3353.46,-227.78 3340.98,-240.26 3340.98,-267.71 3340.98,-553.45 3293.56,-600.86 3287.32,-607.1 3287.32,-681.97 3287.32,-699.44 3307.29,-719.4 3308.54,-720.65 3603.01,-720.65 3636.7,-720.65 3651.67,-705.68 3660.4,-696.94 3660.4,-597.12 3660.4,-568.42 3682.86,-545.96 3719.05,-509.78 3927.42,-509.78 3944.89,-509.78 3957.37,-497.3 3957.37,-373.77 3957.37,-307.64 3941.15,-291.42 3928.67,-278.94 3812.63,-278.94 3645.43,-278.94 3593.02,-226.54

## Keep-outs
Keep-Out Layer:
  the board outline again, w5

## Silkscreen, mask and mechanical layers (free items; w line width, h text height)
Top Overlay:
  drawing of 460 lines, arcs and shapes, not listed
  text "137MM" at 2439.73,223.12 h30
  text "LKS_DEMO_V5.0_20200620" at 3189.3,-29.43 h40
  text "48V" at 1091.56,-33.19 h40
  text "HALL" at 4813.98,-118.06 h40
  text "V" at 2383.75,-147.29 h100
  text "W" at 3464.34,-147.29 h100
  text "U" at 1244.36,-155.11 h100
  text "5VH" at 5095.07,-254.69 h40
  text "U" at 5124.52,-358.34 h40
  text "V" at 5125.13,-458.67 h40
  text "W" at 5129.41,-557.44 h40
  text "GND" at 5095.96,-657.17 h40
  text "RX0" at 5107.14,-942.41 h40
  text "PGND" at 4270.43,-961.6 h30
  text "TX0" at 5105,-1040.19 h40
  text "+48V" at 29.18,-1084.28 h80 r90
  text "GND" at 5103.92,-1140.09 h40
  text "GND" at 4120.67,-1250 h40
  text "R4" at 4733.7,-1383.1 h40
  text "GND" at 19.26,-1542.46 h80 r90
  text "85" at -230.96,-1738.43 h30 r90
  text "STOP" at 4687.64,-1887.39 h40
  text "POWER" at -51.05,-1924.69 h40 r90
  text "15V" at -74.39,-2418.01 h40
  text "START" at 4684.68,-2429.45 h40
  text "5V" at 1402.31,-2579.92 h40
  text "5V" at -41.77,-2649.09 h40
  text "5V" at 1404.11,-2673.72 h40
  text "5V" at 1720.37,-2679.13 h40
  text "P5、P6、P7跳帽说明：" at 1843.69,-2905.51 h100
  text "跳帽连接右端是三电阻采样" at 1838.89,-2995.03 h100
  text "GND" at 4725.8,-3036.04 h40
  text "跳帽连接左端是三相MOS内阻采样" at 1838.08,-3081.1 h100
  text "GND" at 194.74,-3130.2 h40
  text "20200430" at 3464.56,-3332.28 h60
Bottom Overlay:
  drawing of 452 lines, arcs and shapes, not listed
Top Solder:
  circle w78.74: c-8.21,-3104.1 r17.13
  circle w78.74: c5188.98,-7.92 r17.13
  circle w78.74: c5128.7,-3120.51 r17.13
